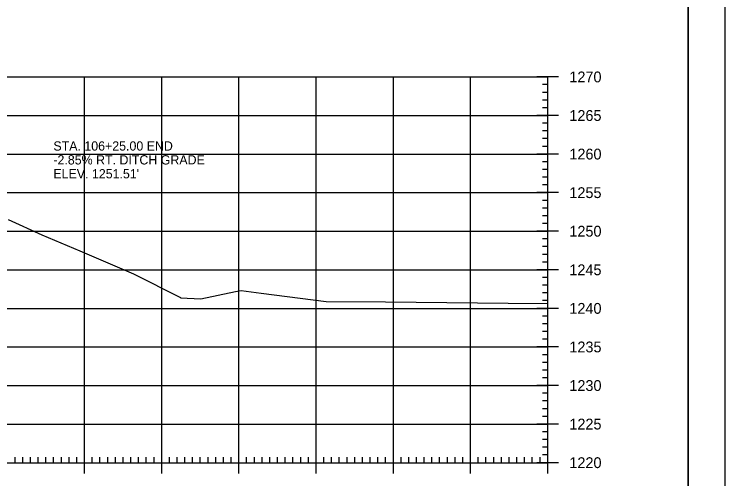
# Model space of a CAD drawing. Extents: x 1406028 to 1412453, y 321733 to 325986.
# Drawn here: x 1406660.8 to 1406752.8, y 322452.2 to 322512.5 of the extents above; entities that cross this region are included whole.
import ezdxf

# ---------------------------------------------------------------- set-up
doc = ezdxf.new("R2010")
doc.units = 0
for name, color, linetype in [('R_Axis', 7, 'Continuous'), ('R_Axis Annot', 7, 'Continuous'), ('R_Border', 7, 'Continuous'), ('R_Drive', 7, 'Continuous'), ('R_Exist Surface', 7, 'Continuous'), ('R_Grid', 7, 'Continuous'), ('R_No Plot', 7, 'Continuous')]:
    doc.layers.add(name, color=color, linetype=linetype)

msp = doc.modelspace()

# ---------------------------------------------------------------- linework, layer by layer
at = {"layer": 'R_Axis'}
for p, q in [((1406731.283, 322504.328), (1406728.483, 322504.328)), ((1406729.883, 322454.328), (1406729.883, 322504.328)), ((1406729.883, 322503.328), (1406729.183, 322503.328)), ((1406729.883, 322502.328), (1406729.183, 322502.328)), ((1406729.883, 322501.328), (1406729.183, 322501.328)), ((1406729.883, 322500.328), (1406729.183, 322500.328)), ((1406731.283, 322499.328), (1406728.483, 322499.328)), ((1406729.883, 322498.328), (1406729.183, 322498.328)), ((1406729.883, 322497.328), (1406729.183, 322497.328)), ((1406729.883, 322496.328), (1406729.183, 322496.328)), ((1406729.883, 322495.328), (1406729.183, 322495.328)), ((1406731.283, 322494.328), (1406728.483, 322494.328)), ((1406729.883, 322493.328), (1406729.183, 322493.328)), ((1406729.883, 322492.328), (1406729.183, 322492.328)), ((1406729.883, 322491.328), (1406729.183, 322491.328)), ((1406729.883, 322490.328), (1406729.183, 322490.328)), ((1406731.283, 322489.328), (1406728.483, 322489.328)), ((1406729.883, 322488.328), (1406729.183, 322488.328)), ((1406729.883, 322487.328), (1406729.183, 322487.328)), ((1406729.883, 322486.328), (1406729.183, 322486.328)), ((1406729.883, 322485.328), (1406729.183, 322485.328)), ((1406731.283, 322484.328), (1406728.483, 322484.328)), ((1406729.883, 322483.328), (1406729.183, 322483.328)), ((1406729.883, 322482.328), (1406729.183, 322482.328)), ((1406729.883, 322481.328), (1406729.183, 322481.328)), ((1406729.883, 322480.328), (1406729.183, 322480.328)), ((1406731.283, 322479.328), (1406728.483, 322479.328)), ((1406729.883, 322478.328), (1406729.183, 322478.328)), ((1406729.883, 322477.328), (1406729.183, 322477.328)), ((1406729.883, 322476.328), (1406729.183, 322476.328)), ((1406729.883, 322475.328), (1406729.183, 322475.328)), ((1406731.283, 322474.328), (1406728.483, 322474.328)), ((1406729.883, 322473.328), (1406729.183, 322473.328)), ((1406729.883, 322472.328), (1406729.183, 322472.328)), ((1406729.883, 322471.328), (1406729.183, 322471.328)), ((1406729.883, 322470.328), (1406729.183, 322470.328)), ((1406731.283, 322469.328), (1406728.483, 322469.328)), ((1406729.883, 322468.328), (1406729.183, 322468.328)), ((1406729.883, 322467.328), (1406729.183, 322467.328)), ((1406729.883, 322466.328), (1406729.183, 322466.328)), ((1406729.883, 322465.328), (1406729.183, 322465.328)), ((1406731.283, 322464.328), (1406728.483, 322464.328)), ((1406729.883, 322463.328), (1406729.183, 322463.328)), ((1406729.883, 322462.328), (1406729.183, 322462.328)), ((1406729.883, 322461.328), (1406729.183, 322461.328)), ((1406729.883, 322460.328), (1406729.183, 322460.328)), ((1406731.283, 322459.328), (1406728.483, 322459.328)), ((1406729.883, 322458.328), (1406729.183, 322458.328)), ((1406729.883, 322457.328), (1406729.183, 322457.328)), ((1406729.883, 322456.328), (1406729.183, 322456.328)), ((1406660.883, 322454.328), (1406660.883, 322455.028)), ((1406661.883, 322454.328), (1406661.883, 322455.028)), ((1406662.883, 322454.328), (1406662.883, 322455.028)), ((1406663.883, 322454.328), (1406663.883, 322455.028)), ((1406664.883, 322454.328), (1406664.883, 322455.028)), ((1406665.883, 322454.328), (1406665.883, 322455.028)), ((1406666.883, 322454.328), (1406666.883, 322455.028)), ((1406667.883, 322454.328), (1406667.883, 322455.028)), ((1406668.883, 322454.328), (1406668.883, 322455.028)), ((1406669.883, 322452.928), (1406669.883, 322455.728)), ((1406670.883, 322454.328), (1406670.883, 322455.028)), ((1406671.883, 322454.328), (1406671.883, 322455.028)), ((1406672.883, 322454.328), (1406672.883, 322455.028)), ((1406673.883, 322454.328), (1406673.883, 322455.028)), ((1406674.883, 322454.328), (1406674.883, 322455.028)), ((1406675.883, 322454.328), (1406675.883, 322455.028)), ((1406676.883, 322454.328), (1406676.883, 322455.028)), ((1406677.883, 322454.328), (1406677.883, 322455.028)), ((1406678.883, 322454.328), (1406678.883, 322455.028)), ((1406679.883, 322452.928), (1406679.883, 322455.728)), ((1406680.883, 322454.328), (1406680.883, 322455.028)), ((1406681.883, 322454.328), (1406681.883, 322455.028)), ((1406682.883, 322454.328), (1406682.883, 322455.028)), ((1406683.883, 322454.328), (1406683.883, 322455.028)), ((1406684.883, 322454.328), (1406684.883, 322455.028)), ((1406685.883, 322454.328), (1406685.883, 322455.028)), ((1406686.883, 322454.328), (1406686.883, 322455.028)), ((1406687.883, 322454.328), (1406687.883, 322455.028)), ((1406688.883, 322454.328), (1406688.883, 322455.028)), ((1406689.883, 322452.928), (1406689.883, 322455.728)), ((1406690.883, 322454.328), (1406690.883, 322455.028)), ((1406691.883, 322454.328), (1406691.883, 322455.028)), ((1406692.883, 322454.328), (1406692.883, 322455.028)), ((1406693.883, 322454.328), (1406693.883, 322455.028)), ((1406694.883, 322454.328), (1406694.883, 322455.028)), ((1406695.883, 322454.328), (1406695.883, 322455.028)), ((1406696.883, 322454.328), (1406696.883, 322455.028)), ((1406697.883, 322454.328), (1406697.883, 322455.028)), ((1406698.883, 322454.328), (1406698.883, 322455.028)), ((1406699.883, 322452.928), (1406699.883, 322455.728)), ((1406700.883, 322454.328), (1406700.883, 322455.028)), ((1406701.883, 322454.328), (1406701.883, 322455.028)), ((1406702.883, 322454.328), (1406702.883, 322455.028)), ((1406703.883, 322454.328), (1406703.883, 322455.028)), ((1406704.883, 322454.328), (1406704.883, 322455.028)), ((1406705.883, 322454.328), (1406705.883, 322455.028)), ((1406706.883, 322454.328), (1406706.883, 322455.028)), ((1406707.883, 322454.328), (1406707.883, 322455.028)), ((1406708.883, 322454.328), (1406708.883, 322455.028)), ((1406709.883, 322452.928), (1406709.883, 322455.728)), ((1406710.883, 322454.328), (1406710.883, 322455.028)), ((1406711.883, 322454.328), (1406711.883, 322455.028)), ((1406712.883, 322454.328), (1406712.883, 322455.028)), ((1406713.883, 322454.328), (1406713.883, 322455.028)), ((1406714.883, 322454.328), (1406714.883, 322455.028)), ((1406715.883, 322454.328), (1406715.883, 322455.028)), ((1406716.883, 322454.328), (1406716.883, 322455.028)), ((1406717.883, 322454.328), (1406717.883, 322455.028)), ((1406718.883, 322454.328), (1406718.883, 322455.028)), ((1406719.883, 322452.928), (1406719.883, 322455.728)), ((1406720.883, 322454.328), (1406720.883, 322455.028)), ((1406721.883, 322454.328), (1406721.883, 322455.028)), ((1406722.883, 322454.328), (1406722.883, 322455.028)), ((1406723.883, 322454.328), (1406723.883, 322455.028)), ((1406724.883, 322454.328), (1406724.883, 322455.028)), ((1406725.883, 322454.328), (1406725.883, 322455.028)), ((1406726.883, 322454.328), (1406726.883, 322455.028)), ((1406727.883, 322454.328), (1406727.883, 322455.028)), ((1406728.883, 322454.328), (1406728.883, 322455.028)), ((1406729.883, 322455.328), (1406729.183, 322455.328)), ((1406729.883, 322452.928), (1406729.883, 322455.728)), ((1406449.883, 322454.328), (1406729.883, 322454.328)), ((1406731.283, 322454.328), (1406728.483, 322454.328))]:
    msp.add_line(p, q, dxfattribs=at)
at = {"layer": 'R_Border'}
msp.add_line((1406748.063, 322363.328), (1406748.063, 322568.788), dxfattribs=at)
at = {"layer": 'R_Exist Surface'}
msp.add_lwpolyline([(1406660.008, 322485.852), (1406664.349, 322483.853), (1406669.264, 322481.788), (1406676.213, 322478.815), (1406682.294, 322475.722), (1406682.311, 322475.713), (1406682.316, 322475.713), (1406684.933, 322475.583), (1406689.444, 322476.522), (1406690.169, 322476.651), (1406692.764, 322476.301), (1406701.187, 322475.238), (1406708.871, 322475.17), (1406724.74, 322475.022), (1406729.883, 322474.956)], dxfattribs=at)
at = {"layer": 'R_Grid'}
for p, q in [((1406449.883, 322504.328), (1406729.883, 322504.328)), ((1406669.883, 322454.328), (1406669.883, 322504.328)), ((1406679.883, 322454.328), (1406679.883, 322504.328)), ((1406689.883, 322454.328), (1406689.883, 322504.328)), ((1406699.883, 322454.328), (1406699.883, 322504.328)), ((1406709.883, 322454.328), (1406709.883, 322504.328)), ((1406719.883, 322454.328), (1406719.883, 322504.328)), ((1406729.883, 322454.328), (1406729.883, 322504.328)), ((1406449.883, 322499.328), (1406729.883, 322499.328)), ((1406449.883, 322494.328), (1406729.883, 322494.328)), ((1406449.883, 322489.328), (1406729.883, 322489.328)), ((1406449.883, 322484.328), (1406729.883, 322484.328)), ((1406449.883, 322479.328), (1406729.883, 322479.328)), ((1406449.883, 322474.328), (1406729.883, 322474.328)), ((1406449.883, 322469.328), (1406729.883, 322469.328)), ((1406449.883, 322464.328), (1406729.883, 322464.328)), ((1406449.883, 322459.328), (1406729.883, 322459.328)), ((1406449.883, 322454.328), (1406729.883, 322454.328))]:
    msp.add_line(p, q, dxfattribs=at)
at = {"layer": 'R_No Plot'}
for points in [[(1406419.475, 322572.682), (1406752.815, 322572.682), (1406752.815, 322359.345), (1406419.475, 322359.345)], [(1406665.803, 322568.788), (1406685.423, 322568.788), (1406685.423, 322558.908), (1406701.535, 322558.908), (1406724.734, 322558.908), (1406724.734, 322534.575), (1406748.063, 322534.575), (1406748.063, 322363.328), (1406431.883, 322363.328), (1406431.883, 322568.788)]]:
    msp.add_lwpolyline(points, close=True, dxfattribs=at)

# ---------------------------------------------------------------- texts
at = {"layer": 'R_Axis Annot'}
for s, p in [('1270', (1406732.683, 322503.628)), ('1265', (1406732.683, 322498.628)), ('1260', (1406732.683, 322493.628)), ('1255', (1406732.683, 322488.628)), ('1250', (1406732.683, 322483.628)), ('1245', (1406732.683, 322478.628)), ('1240', (1406732.683, 322473.628)), ('1235', (1406732.683, 322468.628)), ('1230', (1406732.683, 322463.628)), ('1225', (1406732.683, 322458.628)), ('1220', (1406732.683, 322453.628))]:
    msp.add_text(s, height=1.4, dxfattribs=at).set_placement(p)
at = {"layer": 'R_Drive'}
for s, p in [('STA. 106+25.00 END', (1406665.848, 322494.78)), ('-2.85% RT. DITCH GRADE', (1406665.848, 322492.98)), ("ELEV. 1251.51'", (1406665.848, 322491.18))]:
    msp.add_text(s, height=1.2, dxfattribs=at).set_placement(p)
at = {"layer": 'R_No Plot'}
for p in [(1406664.306, 322483.803), (1406676.17, 322478.765), (1406690.126, 322476.601), (1406682.269, 322475.663), (1406684.89, 322475.533), (1406701.144, 322475.188), (1406724.697, 322474.972)]:
    msp.add_text('+', height=0.1, dxfattribs=at).set_placement(p)

doc.saveas('drawing.dxf')
